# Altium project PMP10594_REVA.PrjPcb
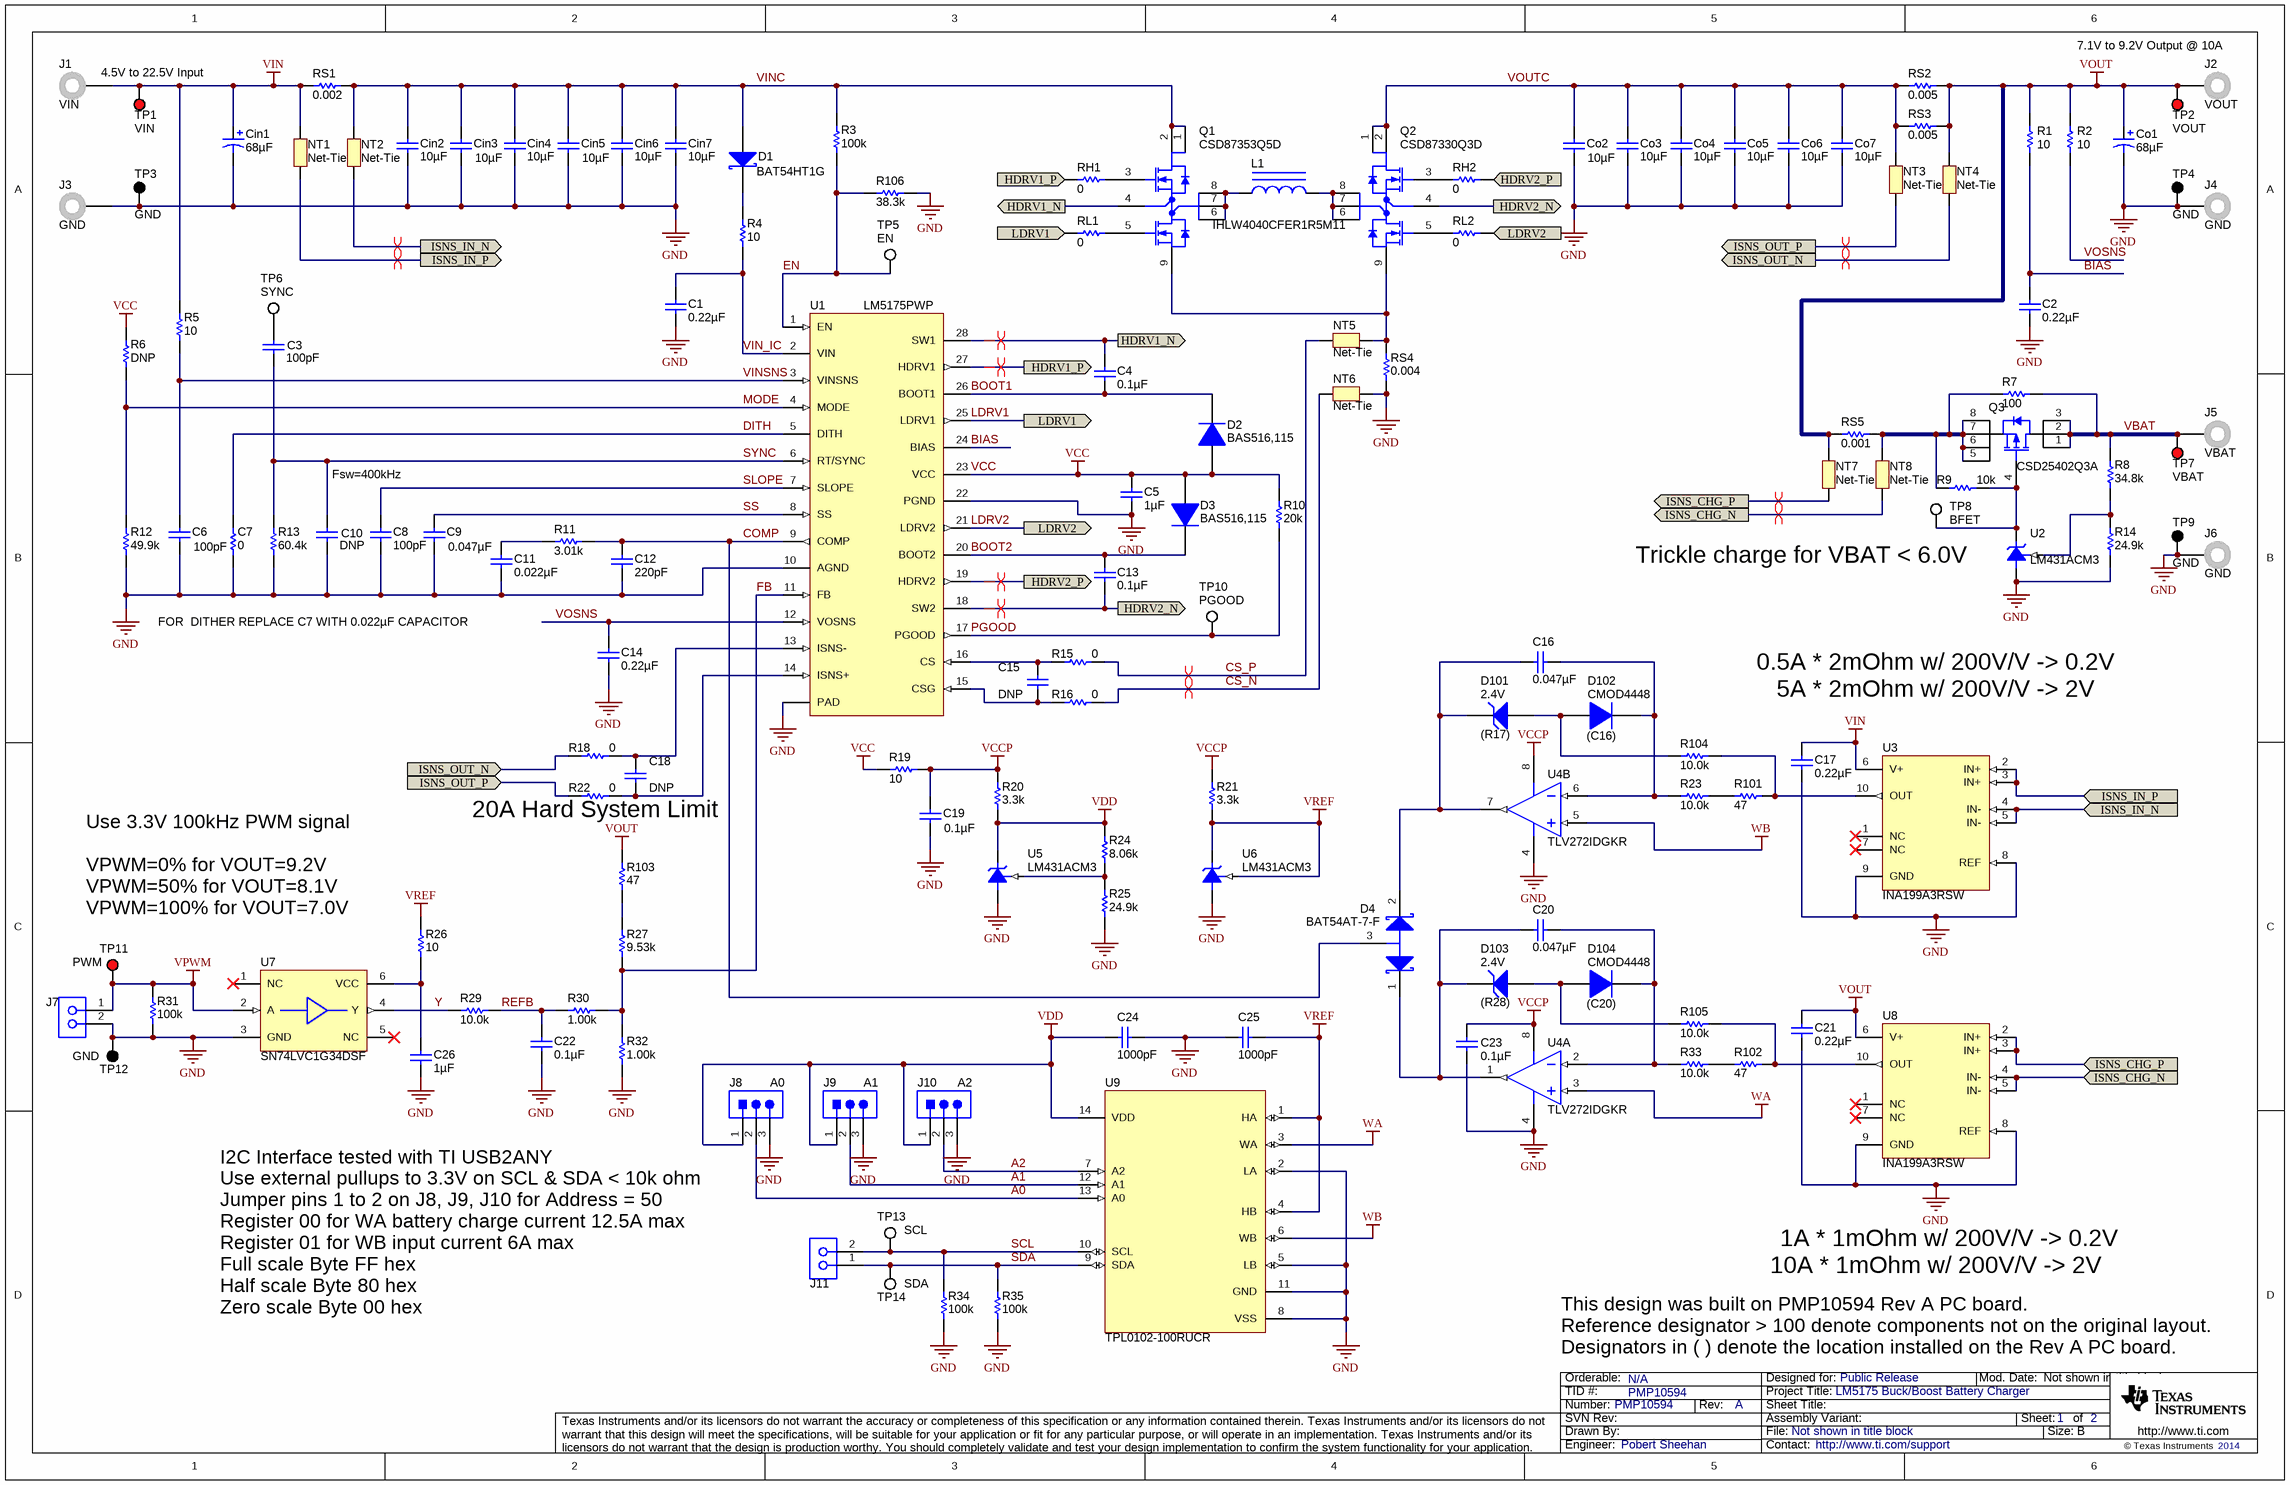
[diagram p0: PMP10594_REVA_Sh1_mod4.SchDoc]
TID: PMP10594; TechSupport: http://www.ti.com/support; SCH_Rev: A; PRJ_Title: LM5175 Buck/Boost Battery Charger; PRJ_Number: PMP10594; PRJ_Engineer: Pobert Sheehan; PRJ_Customer: Public Release; PCB_Rev: A; PCB_Layout: Robert Sheehan; EVM_Orderable: N/A; CopyrightYear: 2014
2 sheets, 158 parts. Net scope: flat (ports and power ports of the same name join across sheets).
Board file: PMP10594_REVA.PcbDoc
Sheets:
  PMP10594_REVA_Sh1_mod4.SchDoc
  PMP10594_REVA_Sh2.SchDoc

## Sheet PMP10594_REVA_Sh1_mod4.SchDoc
size 431 x 279 mm; Date: Not shown in title block; ApprovedBy: Not shown in title block; CheckedBy: Not shown in title block; Author: Not shown in title block; CompanyName: Not shown in title block; Engineer: Not shown in title block; Organization: Not shown in title block; Address1: Not shown in title block; Address2: Not shown in title block; Address3: Not shown in title block; Address4: Not shown in title block; DocumentNumber: 1; Revision: Use project parameter SCH_Rev; SheetNumber: 1; SheetTotal: 2; PageSetup: Record=PageOptions¦CenterHorizontal=True¦CenterVertical=True¦PrintScale=1.00¦XCorrection=1.00¦YCorrection=1.00¦PrintKind=0¦BorderSize=5000000¦LeftOffset=0¦BottomOffset=0¦Orientation=2¦PaperLength=1000¦PaperWidth=1000¦Scale=100¦PaperSource=15¦PrintQuality=600¦MediaType=1¦DitherType=10¦PaperKind=Letter¦PrintScaleMode=1

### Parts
C1  ValueDisplayed: 0.22µF  [0603L]  (hidden comment: C1608X7R1H224K080AB)
C2  ValueDisplayed: 0.22µF  [0603L]  (hidden comment: C1608X7R1H224K080AB)
C3  ValueDisplayed: 100pF  [0603L]  (hidden comment: CGA3E2NP01H101J080AA)
C4  ValueDisplayed: 0.1µF  [0603L]  (hidden comment: 06033C104JAT2A)
C5  ValueDisplayed: 1µF  [0603L]  (hidden comment: GRM188R71C105KA12D)
C6  ValueDisplayed: 100pF  [0603L]  (hidden comment: GRM1885C1H101JA01D)
C7  ValueDisplayed: 0  [0603L]  (hidden comment: CRCW06030000Z0EA)
C8  ValueDisplayed: 100pF  [0603L]  (hidden comment: GRM1885C1H101JA01D)
C9  ValueDisplayed: 0.047µF  [0603L]  (hidden comment: GRM188R71H473KA61D)
C10  DNP  [0603L]
C11  ValueDisplayed: 0.022µF  [0603L]  (hidden comment: GRM188R71H223KA01D)
C12  ValueDisplayed: 220pF  [0603L]  (hidden comment: GRM1885C1H221JA01D)
C13  ValueDisplayed: 0.1µF  [0603L]  (hidden comment: 06033C104JAT2A)
C14  ValueDisplayed: 0.22µF  [0603L]  (hidden comment: C1608X7R1H224K080AB)
C15  DNP  [0603L]
C16  ValueDisplayed: 0.047µF  [0603L]  (hidden comment: GRM188R71H473KA61D)
C17  ValueDisplayed: 0.22µF  [0603_HV]  (hidden comment: C1608X7R1H224K080AB)
C18  DNP  [0603L]
C19  ValueDisplayed: 0.1µF  [0603L]  (hidden comment: 06033C104JAT2A)
C20  ValueDisplayed: 0.047µF  [0603L]  (hidden comment: GRM188R71H473KA61D)
C21  ValueDisplayed: 0.22µF  [0603_HV]  (hidden comment: C1608X7R1H224K080AB)
C22  ValueDisplayed: 0.1µF  [0603L]  (hidden comment: 06033C104JAT2A)
C23  ValueDisplayed: 0.1µF  [0603L]  (hidden comment: 06033C104JAT2A)
C24  ValueDisplayed: 1000pF  [0603L]  (hidden comment: GRM188R71H102KA01D)
C25  ValueDisplayed: 1000pF  [0603L]  (hidden comment: GRM188R71H102KA01D)
C26  ValueDisplayed: 1µF  [0603L]  (hidden comment: GRM188R71C105KA12D)
Cin1  ValueDisplayed: 68µF  [SM_RADIAL_8MM]  (hidden comment: EEHZC1H680P)
Cin2  ValueDisplayed: 10µF  [1210L]  (hidden comment: GRM32ER71H106KA12L)
Cin3  ValueDisplayed: 10µF  [1210L]  (hidden comment: GRM32ER71H106KA12L)
Cin4  ValueDisplayed: 10µF  [1210L]  (hidden comment: GRM32ER71H106KA12L)
Cin5  ValueDisplayed: 10µF  [1210L]  (hidden comment: GRM32ER71H106KA12L)
Cin6  ValueDisplayed: 10µF  [1210L]  (hidden comment: GRM32ER71H106KA12L)
Cin7  ValueDisplayed: 10µF  [1210L]  (hidden comment: GRM32ER71H106KA12L)
Co1  ValueDisplayed: 68µF  [SM_RADIAL_8MM]  (hidden comment: EEHZC1H680P)
Co2  ValueDisplayed: 10µF  [1210L]  (hidden comment: GRM32ER71H106KA12L)
Co3  ValueDisplayed: 10µF  [1210L]  (hidden comment: GRM32ER71H106KA12L)
Co4  ValueDisplayed: 10µF  [1210L]  (hidden comment: GRM32ER71H106KA12L)
Co5  ValueDisplayed: 10µF  [1210L]  (hidden comment: GRM32ER71H106KA12L)
Co6  ValueDisplayed: 10µF  [1210L]  (hidden comment: GRM32ER71H106KA12L)
Co7  ValueDisplayed: 10µF  [1210L]  (hidden comment: GRM32ER71H106KA12L)
D1  BAT54HT1G  [sod-323]
D2  BAS516,115  [SOD-523]
D3  BAS516,115  [SOD-523]
D4  BAT54AT-7-F  [SOT-523]
D101  (R17)  value 2.4V  [sod-323]
D102  (C16)  PartNumber: CMOD4448  [sod-523]
D103  (R28)  value 2.4V  [sod-323]
D104  (C20)  PartNumber: CMOD4448  [sod-523]
J1  VIN  [Johnson_108-0740-001]
J2  VOUT  [Johnson_108-0740-001]
J3  GND  [Johnson_108-0740-001]
J4  GND  [Johnson_108-0740-001]
J5  VBAT  [Johnson_108-0740-001]
J6  GND  [Johnson_108-0740-001]
J7  1727010  [PhoenixConact_1727010]  (value not drawn)
J8  A0  [TE_5-146278-3]
J9  A1  [TE_5-146278-3]
J10  A2  [TE_5-146278-3]
J11  1727010  [PhoenixConact_1727010]  (value not drawn)
L1  IHLW4040CFER1R5M11  [IHLW-4040CF]
NT1  Net-Tie  [Net-Tie_10mil]  (net tie, no BOM)
NT2  Net-Tie  [Net-Tie_10mil]  (net tie, no BOM)
NT3  Net-Tie  [Net-Tie_10mil]  (net tie, no BOM)
NT4  Net-Tie  [Net-Tie_10mil]  (net tie, no BOM)
NT5  Net-Tie  [Net-Tie_10mil]  (net tie, no BOM)
NT6  Net-Tie  [Net-Tie_10mil]  (net tie, no BOM)
NT7  Net-Tie  [Net-Tie_10mil]  (net tie, no BOM)
NT8  Net-Tie  [Net-Tie_10mil]  (net tie, no BOM)
Q1  CSD87353Q5D  [TRANS_NexFET_Q5D]
Q2  CSD87330Q3D  [TRANS_NexFET_Q3D]
Q3  CSD25402Q3A  [TRANS_NexFET_Q3A]
R1  value 10  [0603L]  (hidden comment: CRCW060310R0JNEA)
R2  ValueDisplayed: 10  [0603L]  (hidden comment: CRCW060310R0JNEA)
R3  ValueDisplayed: 100k  [0603L]  (hidden comment: CRCW0603100KJNEA)
R4  ValueDisplayed: 10  [0603L]  (hidden comment: CRCW060310R0JNEA)
R5  ValueDisplayed: 10  [0603L]  (hidden comment: CRCW060310R0JNEA)
R6  DNP  [0603L]
R7  ValueDisplayed: 100  [2010]  (hidden comment: CRCW2010100RJNEF)
R8  ValueDisplayed: 34.8k  [0603L]  (hidden comment: CRCW060334K8FKEA)
R9  ValueDisplayed: 10k  [0603L]  (hidden comment: CRCW060310K0JNEA)
R10  ValueDisplayed: 20k  [0603L]  (hidden comment: CRCW060320K0JNEA)
R11  ValueDisplayed: 3.01k  [0603L]  (hidden comment: CRCW06033K01FKEA)
R12  ValueDisplayed: 49.9k  [0603L]  (hidden comment: CRCW060349K9FKEA)
R13  ValueDisplayed: 60.4k  [0603L]  (hidden comment: CRCW060360K4FKEA)
R14  ValueDisplayed: 24.9k  [0603L]  (hidden comment: CRCW060324K9FKEA)
R15  value 0  [0603L]  (hidden comment: CRCW06030000Z0EA)
R16  value 0  [0603L]  (hidden comment: CRCW06030000Z0EA)
R18  value 0  [0603L]  (hidden comment: CRCW06030000Z0EA)
R19  ValueDisplayed: 10  [0603L]  (hidden comment: CRCW060310R0JNEA)
R20  ValueDisplayed: 3.3k  [0603L]  (hidden comment: CRCW06033K30JNEA)
R21  ValueDisplayed: 3.3k  [0603L]  (hidden comment: CRCW06033K30JNEA)
R22  value 0  [0603L]  (hidden comment: CRCW06030000Z0EA)
R23  ValueDisplayed: 10.0k  [0603L]  (hidden comment: CRCW060310K0FKEA)
R24  ValueDisplayed: 8.06k  [0603L]  (hidden comment: CRCW06038K06FKEA)
R25  ValueDisplayed: 24.9k  [0603L]  (hidden comment: CRCW060324K9FKEA)
R26  ValueDisplayed: 10  [0603L]  (hidden comment: CRCW060310R0JNEA)
R27  ValueDisplayed: 9.53k  [0603L]  (hidden comment: CRCW06039K53FKEA)
R29  ValueDisplayed: 10.0k  [0603L]  (hidden comment: CRCW060310K0FKEA)
R30  ValueDisplayed: 1.00k  [0603L]  (hidden comment: CRCW06031K00FKEA)
R31  ValueDisplayed: 100k  [0603L]  (hidden comment: CRCW0603100KJNEA)
R32  ValueDisplayed: 1.00k  [0603L]  (hidden comment: CRCW06031K00FKEA)
R33  ValueDisplayed: 10.0k  [0603L]  (hidden comment: CRCW060310K0FKEA)
R34  ValueDisplayed: 100k  [0603L]  (hidden comment: CRCW0603100KJNEA)
R35  ValueDisplayed: 100k  [0603L]  (hidden comment: CRCW0603100KJNEA)
R101  ValueDisplayed: 47  [0603L]  (hidden comment: CRCW060347R0JNEA)
R102  ValueDisplayed: 47  [0603L]  (hidden comment: CRCW060347R0JNEA)
R103  ValueDisplayed: 47  [0603L]  (hidden comment: CRCW060347R0JNEA)
R104  ValueDisplayed: 10.0k  [0603L]  (hidden comment: CRCW060310K0FKEA)
R105  ValueDisplayed: 10.0k  [0603L]  (hidden comment: CRCW060310K0FKEA)
R106  ValueDisplayed: 38.3k  [0603L]  (hidden comment: CRCW060338K3FKEA)
RH1  value 0  [0603L]  (hidden comment: CRCW06030000Z0EA)
RH2  value 0  [0603L]  (hidden comment: CRCW06030000Z0EA)
RL1  value 0  [0603L]  (hidden comment: CRCW06030000Z0EA)
RL2  value 0  [0603L]  (hidden comment: CRCW06030000Z0EA)
RS1  ValueDisplayed: 0.002  [1206]  (hidden comment: CSNL1206FT2L00)
RS2  ValueDisplayed: 0.005  [2010]  (hidden comment: CSNL2010FT5L00)
RS3  ValueDisplayed: 0.005  [2010]  (hidden comment: CSNL2010FT5L00)
RS4  ValueDisplayed: 0.004  [2512]  (hidden comment: CSNL2512FT4L00)
RS5  ValueDisplayed: 0.001  [2010]  (hidden comment: CSNL2010FT1L00)
TP1  VIN  [Keystone5000]
TP2  VOUT  [Keystone5000]
TP3  GND  [Keystone5001]
TP4  GND  [Keystone5001]
TP5  EN  [Keystone5002]
TP6  SYNC  [Keystone5002]
TP7  VBAT  [Keystone5000]
TP8  BFET  [Keystone5002]
TP9  GND  [Keystone5001]
TP10  PGOOD  [Keystone5002]
TP11  PWM  [Keystone5000]
TP12  GND  [Keystone5001]
TP13  SCL  [Keystone5002]
TP14  SDA  [Keystone5002]
U1  LM5175PWP  [PWP0028F_N]
U2  LM431ACM3  [MF03A_N]
U3  INA199A3RSW  [RSW0010A]
U4  TLV272IDGKR  [DGK0008A_N]  (parts A,B of 2)
U5  LM431ACM3  [MF03A_N]
U6  LM431ACM3  [MF03A_N]
U7  SN74LVC1G34DSF  [DSF0006A]
U8  INA199A3RSW  [RSW0010A]
U9  TPL0102-100RUCR  [RUC0014A]

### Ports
HDRV1_N, HDRV1_P (out), HDRV2_N, HDRV2_P (out), ISNS_CHG_N (in), ISNS_CHG_N (out), ISNS_CHG_P (in), ISNS_CHG_P (out), ISNS_IN_N (in), ISNS_IN_N (out), ISNS_IN_P (in), ISNS_IN_P (out), ISNS_OUT_N (in), ISNS_OUT_N (out), ISNS_OUT_P (in), ISNS_OUT_P (out), LDRV1 (out), LDRV2 (out)

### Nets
GND: C1.2 C2.2 C5.2 C6.1 C7.1 C8.2 C9.2 C10.1 C11.2 C12.2 C14.2 C17.2 C19.2 C21.2 C22.2 C23.2 C24.2 C25.1 C26.2 Cin1.2(-) Cin2.2 Cin3.2 Cin4.2 Cin5.2 Cin6.2 Cin7.2 Co1.2(-) Co2.2 Co3.2 Co4.2 Co5.2 Co6.2 Co7.2 J3.1 J4.1 J6.1 J7.2 J8.3 J9.3 J10.3 NT6.1 R12.1 R13.1 R14.1 R25.1 R31.1 R32.1 R34.1 R35.1 R106.1 RS4.1 TP3.1 TP4.1 TP9.1 TP12.1 U1.10(AGND) U1.22(PGND) U1.29(PAD) U2.3(A) U3.8(REF) U3.9(GND) U4.4(GND) U5.3(A) U6.3(A) U7.3(GND) U8.8(REF) U8.9(GND) U9.2(LA) U9.5(LB) U9.8(VSS) U9.11(GND)
VCC: C5.1 D2.2(A) D3.2(A) R6.2 R10.2 R19.2 U1.23(VCC)
VCCP: C19.1 C23.1 R19.1 R20.1 R21.1 U4.8(VDD)
VDD: C24.1 J8.1 J9.1 J10.1 R20.2 R24.2 U5.1(K) U9.14(VDD)
VIN: C17.1 Cin1.1(+) J1.1 NT1.1 R5.1 RS1.1 TP1.1 U3.6(V+)
VOUT: C21.1 Co1.1(+) J2.1 NT4.2 NT7.2 R1.2 R2.2 R103.1 RS2.2 RS3.2 RS5.1 TP2.1 U8.6(V+)
VPWM: J7.1 R31.2 TP11.1 U7.2(A)
VREF: C25.2 R21.2 R26.2 U6.1(K) U6.2(REF) U9.1(HA) U9.4(HB)
WA: U4.3(IN1+) U9.3(WA)
WB: U4.5(IN2+) U9.6(WB)
A0: J8.2 U9.13(A0)
A1: J9.2 U9.12(A1)
A2: J10.2 U9.7(A2)
BIAS: C2.1 R1.1 U1.24(BIAS)
BOOT1: C4.1 D2.1(K) U1.26(BOOT1)
BOOT2: C13.2 D3.1(K) U1.20(BOOT2)
COMP: C12.1 D4.3(K) R11.2 U1.9(COMP)
CS_N: NT6.2 R16.2
CS_P: NT5.2 R15.2
DITH: C7.2 U1.5(DITH)
EN: R3.1 R106.2 TP5.1 U1.1(EN)
FB: R27.1 R30.2 R32.2 U1.11(FB)
HDRV1_N: C4.2 Q1.4(TGR) U1.28(SW1) ; port HDRV1_N
HDRV1_P: RH1.1 U1.27(HDRV1) ; port HDRV1_P
HDRV2_N: C13.1 Q2.4(TGR) U1.18(SW2) ; port HDRV2_N
HDRV2_P: RH2.2 U1.19(HDRV2) ; port HDRV2_P
ISNS_CHG_N: NT8.1 U8.4(IN-) U8.5(IN-) ; port ISNS_CHG_N
ISNS_CHG_P: NT7.1 U8.2(IN+) U8.3(IN+) ; port ISNS_CHG_P
ISNS_IN_N: NT2.1 U3.4(IN-) U3.5(IN-) ; port ISNS_IN_N
ISNS_IN_P: NT1.2 U3.2(IN+) U3.3(IN+) ; port ISNS_IN_P
ISNS_OUT_N: NT4.1 R18.1 ; port ISNS_OUT_N
ISNS_OUT_P: NT3.1 R22.1 ; port ISNS_OUT_P
LDRV1: RL1.1 U1.25(LDRV1) ; port LDRV1
LDRV2: RL2.2 U1.21(LDRV2) ; port LDRV2
MODE: R6.1 R12.2 U1.4(MODE)
PGOOD: R10.1 TP10.1 U1.17(PGOOD)
REFB: C22.1 R29.1 R30.1
SCL: J11.2 R34.2 TP13.1 U9.10(SCL)
SDA: J11.1 R35.2 TP14.1 U9.9(SDA)
SLOPE: C8.1 U1.7(SLOPE)
SS: C9.1 U1.8(SS)
SYNC: C3.2 C10.2 R13.2 U1.6(RT/SYNC)
VBAT: J5.1 Q3.1(D) Q3.2(D) Q3.3(D) R7.2 R8.2 TP7.1
VIN_IC: C1.1 R4.1 U1.2(VIN)
VINC: Cin2.1 Cin3.1 Cin4.1 Cin5.1 Cin6.1 Cin7.1 D1.2(A) NT2.2 Q1.1(VIN) Q1.2(VIN) R3.2 RS1.2
VINSNS: C6.2 R5.2 U1.3(VINSNS)
VOSNS: C14.1 R2.1 U1.12(VOSNS)
VOUTC: Co2.1 Co3.1 Co4.1 Co5.1 Co6.1 Co7.1 NT3.2 Q2.1(VIN) Q2.2(VIN) RS2.1 RS3.1
Y: R29.2 U7.4(Y)
NetC3_1: C3.1 TP6.1
NetC11_1: C11.1 R11.1
NetC15_1: C15.1 R15.1 U1.16(CS)
NetC15_2: C15.2 R16.1 U1.15(CSG)
NetC16_1: C16.1 D4.2(A2) D101.1(K) U4.7(OUT2)
NetC16_2: C16.2 D102.1(K) R23.1 U4.6(IN2-)
NetC18_1: C18.1 R18.2 U1.13(ISNS-)
NetC18_2: C18.2 R22.2 U1.14(ISNS+)
NetC20_1: C20.1 D4.1(A1) D103.1(K) U4.1(OUT1)
NetC20_2: C20.2 D104.1(K) R33.1 U4.2(IN1-)
NetC26_1: C26.1 R26.1 U7.6(VCC)
NetD1_1: D1.1(K) R4.2
NetD101_2: D101.2(A) D102.2(A) R104.1
NetD103_2: D103.2(A) D104.2(A) R105.1
NetL1_1: L1.1 Q1.6(VSW) Q1.7(VSW) Q1.8(VSW)
NetL1_2: L1.2 Q2.6(VSW) Q2.7(VSW) Q2.8(VSW)
NetNT5_1: NT5.1 Q1.9(PGND) Q2.9(PGND) RS4.2
NetNT8_2: NT8.2 Q3.5(S) Q3.6(S) Q3.7(S) Q3.8(S) R7.1 R9.1 RS5.2
NetQ1_3: Q1.3(TG) RH1.2
NetQ1_5: Q1.5(BG) RL1.2
NetQ2_3: Q2.3(TG) RH2.1
NetQ2_5: Q2.5(BG) RL2.1
NetQ3_4: Q3.4(G) R9.2 TP8.1 U2.1(K)
NetR8_1: R8.1 R14.2 U2.2(REF)
NetR23_2: R23.2 R101.2
NetR24_1: R24.1 R25.2 U5.2(REF)
NetR27_2: R27.2 R103.2
NetR33_2: R33.2 R102.2
NetR101_1: R101.1 R104.2 U3.10(OUT)
NetR102_1: R102.1 R105.2 U8.10(OUT)

Not connected (* = marked no-connect by the designer): U3 1(NC)* 7(NC)*; U7 1(NC)* 5(NC)*; U8 1(NC)* 7(NC)*

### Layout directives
differential pair: CS_N, CS_P, HDRV1_N, HDRV1_P, HDRV2_N, HDRV2_P, ISNS_CHG_N, ISNS_CHG_P, ISNS_IN_N, ISNS_IN_P, ISNS_OUT_N, ISNS_OUT_P

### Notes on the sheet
- 4.5V to 22.5V Input
- 7.1V to 9.2V Output @ 10A
- Fsw=400kHz
- Trickle charge for VBAT < 6.0V
- FOR  DITHER REPLACE C7 WITH 0.022µF CAPACITOR
- 0.5A * 2mOhm w/ 200V/V -> 0.2V
- 5A * 2mOhm w/ 200V/V -> 2V
- (near R22) 20A Hard System Limit
- Use 3.3V 100kHz PWM signal
  VPWM=0% for VOUT=9.2V
  VPWM=50% for VOUT=8.1V
  VPWM=100% for VOUT=7.0V
- 1A * 1mOhm w/ 200V/V -> 0.2V
- 10A * 1mOhm w/ 200V/V -> 2V
- (near J8) I2C Interface tested with TI USB2ANY
  Use external pullups to 3.3V on SCL & SDA < 10k ohm
  Jumper pins 1 to 2 on J8, J9, J10 for Address = 50
  Register 00 for WA battery charge current 12.5A max
  Register 01 for WB input current 6A max
  Full scale Byte FF hex
  Half scale Byte 80 hex
  Zero scale Byte 00 hex
- This design was built on PMP10594 Rev A PC board.
  Reference designator > 100 denote components not on the original layout.
  Designators in ( ) denote the location installed on the Rev A PC board.

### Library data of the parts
C1 C2 C17 C21 = C1608X7R1H224K080AB: CAP, CERM, 0.22uF, 50V, +/-10%, X7R, 0603; Manufacturer: TDK; Polarized: N; CompType: Capacitor; U/M: EA; Cap_F: 0.00000022; Tolerance_%: 10; Value1: Unknown; VDC_V: 50; TaMin_C: -55; TaMax_C: 125; Cap_Case: 0603
C3 = CGA3E2NP01H101J080AA: CAP, CERM, 100pF, 50V, +/-5%, C0G/NP0, 0603; Manufacturer: TDK; Polarized: N; CompType: Capacitor; U/M: EA; Cap_F: 0.0000000001; Tolerance_%: 5; Value1: Unknown; VDC_V: 50; TaMin_C: -55; TaMax_C: 150; Cap_Case: 0603
C4 C13 C19 C22 C23 = 06033C104JAT2A: CAP, CERM, 0.1 µF, 25 V, +/- 5%, X7R, 0603; Manufacturer: AVX; Polarized: N; CompType: Capacitor; Value: 0.1uF; U/M: EA; Cap_F: 0.0000001; Tolerance_%: 5; ESR_ohm: 0.05; Value1: 0.05 ohm; VDC_V: 25; Value2: 25V; TaMin_C: -55; TaMax_C: 125; Cap_Case: 0603
C5 = GRM188R71C105KA12D: CAP, CERM, 1uF, 16V, +/-10%, X7R, 0603; Manufacturer: MuRata; Polarized: N; CompType: Capacitor; U/M: EA; Cap_F: 0.000001; Tolerance_%: 10; ESR_Ohm: 0.011; Value1: 0.011 ohm; VDC_V: 16; TaMin_C: -55; TaMax_C: 125; Cap_Case: 0603
C6 C10 C15 C18 = GRM1885C1H101JA01D: CAP, CERM, 100pF, 50V, +/-5%, C0G/NP0, 0603; Manufacturer: MuRata; Polarized: N; CompType: Capacitor; U/M: EA; Cap_F: 0.0000000001; Tolerance_%: 5; Value1: Unknown; VDC_V: 50; TaMin_C: -55; TaMax_C: 125; Cap_Case: 0603
C7 = CRCW06030000Z0EA: RES, 0, 5%, 0.1 W, 0603; Manufacturer: Vishay-Dale; CompType: Resistor; Value: 0; Tolerance_%: 5; Value2: 0.1W; VDC_V: 75; TempCo: 200 ppm/C; U/M: EA; Value_Code: 0000; Power_W: 0.1; EIA_Code: E24
C8 = GRM1885C1H101JA01D: CAP, CERM, 100 pF, 50 V, +/- 5%, C0G/NP0, 0603; Manufacturer: MuRata; Polarized: N; CompType: Capacitor; Value: 100pF; U/M: EA; Cap_F: 0.0000000001; Tolerance_%: 5; Value1: Unknown; VDC_V: 50; Value2: 50V; TaMin_C: -55; TaMax_C: 125; Cap_Case: 0603
C9 C16 C20 = GRM188R71H473KA61D: CAP, CERM, 0.047 µF, 50 V, +/- 10%, X7R, 0603; Manufacturer: MuRata; Polarized: N; CompType: Capacitor; Value: 0.047uF; U/M: EA; Cap_F: 0.000000047; Tolerance_%: 10; Value1: Unknown; VDC_V: 50; Value2: 50V; TaMin_C: -55; TaMax_C: 125; Cap_Case: 0603
C11 = GRM188R71H223KA01D: CAP, CERM, 0.022 µF, 50 V, +/- 10%, X7R, 0603; Manufacturer: MuRata; Polarized: N; CompType: Capacitor; Value: 0.022uF; U/M: EA; Cap_F: 0.000000022; Tolerance_%: 10; Value1: Unknown; VDC_V: 50; Value2: 50V; TaMin_C: -55; TaMax_C: 125; Cap_Case: 0603
C12 = GRM1885C1H221JA01D: CAP, CERM, 220 pF, 50 V, +/- 5%, C0G/NP0, 0603; Manufacturer: MuRata; Polarized: N; CompType: Capacitor; Value: 220pF; U/M: EA; Cap_F: 0.00000000022; Tolerance_%: 5; Value1: Unknown; VDC_V: 50; Value2: 50V; TaMin_C: -55; TaMax_C: 125; Cap_Case: 0603
C14 = C1608X7R1H224K080AB: CAP, CERM, 0.22 µF, 50 V, +/- 10%, X7R, 0603; Manufacturer: TDK; Polarized: N; CompType: Capacitor; Value: 0.22uF; U/M: EA; Cap_F: 0.00000022; Tolerance_%: 10; Value1: Unknown; VDC_V: 50; Value2: 50V; TaMin_C: -55; TaMax_C: 125; Cap_Case: 0603
C24 C25 = GRM188R71H102KA01D: CAP, CERM, 1000 pF, 50 V, +/- 10%, X7R, 0603; Manufacturer: MuRata; Polarized: N; CompType: Capacitor; Value: 1000pF; U/M: EA; Cap_F: 0.000000001; Tolerance_%: 10; Value1: Unknown; VDC_V: 50; Value2: 50V; TaMin_C: -55; TaMax_C: 125; Cap_Case: 0603
C26 = GRM188R71C105KA12D: CAP, CERM, 1 µF, 16 V, +/- 10%, X7R, 0603; Manufacturer: MuRata; Polarized: N; CompType: Capacitor; Value: 1uF; U/M: EA; Cap_F: 0.000001; Tolerance_%: 10; ESR_ohm: 0.011; Value1: 0.011 ohm; VDC_V: 16; Value2: 16V; TaMin_C: -55; TaMax_C: 125; Cap_Case: 0603
Cin1 Co1 = EEHZC1H680P: CAP, AL, 68 µF, 50 V, +/- 20%, 30 ohm, SMD; Manufacturer: Panasonic; Polarized: Y; CompType: Capacitor; Value: 68uF; U/M: EA; Cap_F: 0.000068; Tolerance_%: 20; Value1: 30 ohm; VDC_V: 50; Value2: 50V; ESR_ohm: 30; IRMS_A: 1.25; TaMin_C: -55; TaMax_C: 125
Cin2-Cin7 = GRM32ER71H106KA12L: CAP, CERM, 10uF, 50V, +/-10%, X7R, 1210; Manufacturer: MuRata; Polarized: N; CompType: Capacitor; U/M: EA; Cap_F: 0.00001; Tolerance_%: 10; Value1: Unknown; VDC_V: 50; TaMin_C: -55; TaMax_C: 125; Cap_Case: 1210
Co2-Co7 = GRM32ER71H106KA12L: CAP, CERM, 10 µF, 50 V, +/- 10%, X7R, 1210; Manufacturer: MuRata; Polarized: N; CompType: Capacitor; Value: 10uF; U/M: EA; Cap_F: 0.00001; Tolerance_%: 10; Value1: Unknown; VDC_V: 50; Value2: 50V; TaMin_C: -55; TaMax_C: 125; Cap_Case: 1210
D1 = BAT54HT1G: Diode, Schottky, 30V, 0.2A, SOD-323; Manufacturer: ON Semiconductor; U/M: EA; Vf_V: 0.35; Value2: 0.35V; Io_A: 0.2; Vr_V: 30
D2 D3 = BAS516,115: Diode, Switching, 100V, 0.25A, SOD-523; Manufacturer: NXP Semiconductor; U/M: EA; Vf_V: 1.25; Value2: 1.25V; Io_A: 0.25; Vr_V: 100; TJmax_C: 150
D4 = BAT54AT-7-F: Diode, Schottky, 30 V, 0.2 A, SOT-523; Manufacturer: Diodes Inc.; U/M: EA; Vf_V: 0.7; Value: 30V; Value1: 0.2A; Value2: 0.7V; Io_A: 0.2; Vr_V: 30; TJmax_C: 125
D101 D103 = MMSZ5221BS-7-F: Diode, Zener, 2.4 V, 200 mW, SOD-323; Manufacturer: Diodes Inc.; U/M: EA; Value1: 0.2W; SymbolCreator: a0412235; Power_W: 0.2; Vz_V: 2.4; RJA_CperW: 350
D102 D104 = CMDD4448: Diode, Ultrafast, 75 V, 0.25 A, SOD-523; Manufacturer: Central Semiconductor; U/M: EA; Vf_V: 1.2; Value: 75V; Value1: 0.25A; Value2: 1.2V; Io_A: 0.25; Vr_V: 75; TJmax_C: 175
J1-J6 = 108-0740-001: Standard Banana Jack, Uninsulated, 15A; Manufacturer: Emerson Network Power; SymbolCreator: a0412235; CompType: Connector; U/M: EA
J7 J11 = 1727010: Conn Term Block, 2POS, 3.81mm PCB; Manufacturer: Phoenix Contact; CompType: Terminal Block; U/M: EA; Value: 2x1
J8-J10 = 5-146278-3: Header, 100mil, 3x1, Tin, TH; Manufacturer: TE Connectivity; SymbolCreator: a0799628; U/M: EA
L1 = IHLW4040CFER1R5M11: Inductor, Shielded, Powdered Iron, 1.5 µH, 14.5 A, 0.0044 ohm, SMD, Winged Terminal; Manufacturer: Vishay-Dale; Value: 1.5uH; ValueDisplayed: 1.5µH; Ind_H: 1.5E-6; Imax_A: 15; Irms: 20A @ 40C rise; Isat: 14.5A @ 20% inductance drop; DCR_ohm: 0.0044; Value2: 14.5A
NT1-NT8 = Net-Tie: Single point connection between nets.; SymbolCreator: codlsc
Q1 = CSD87353Q5D: Manufacturer: Texas Instruments; Alternate Manufacturer: None; CompType: MOSFET; U/M: EA; ChType: N
Q2 = CSD87330Q3D: MOSFET, N/P-CH, 30 V, 20 A, 3.4x1.4x3.4mm; Manufacturer: Texas Instruments; Alternate Manufacturer: None; SymbolCreator: a0799628; U/M: EA; ChType: N; Value: 30V; VdsMax_V: 30; Value1: ? ohm; Value2: 5.8 nC; QgTyp_nC: 5.8; Vgs_V: 2.1; IdsMax_A: 20
Q3 = CSD25402Q3A: MOSFET, P-CH, -20 V, -15 A, SON 3.3x3.3mm; Manufacturer: Texas Instruments; Alternate Manufacturer: None; SymbolCreator: a0411947; U/M: EA; ChType: P; Value: -20V; Value1: 0.0077 ohm; Rdson45_ohm: 0.0077; Value2: 7.5 nC; QgTyp_nC: 7.5; Vgs_V: 12
R1 = CRCW060310R0JNEA: RES, 10, 5%, 0.1 W, 0603; Manufacturer: Vishay-Dale; CompType: Resistor; Value_Code: 10R0; Tolerance_%: 5; Power_W: 0.1; Value2: 0.1W; VDC_V: 75; TempCo: 200 ppm/C; EIA_Code: E24; U/M: EA
R2 = CRCW060310R0JNEA: RES, 10, 5%, 0.1 W, 0603; Manufacturer: Vishay-Dale; CompType: Resistor; Value_Code: 10R0; Tolerance_%: 5; Power_W: 0.1; Value2: 0.1W; VDC_V: 75; TempCo: 200 ppm/C; EIA_Code: E24; U/M: EA; Value: 10
R3 R31 R34 R35 = CRCW0603100KJNEA: RES, 100 k, 5%, 0.1 W, 0603; Manufacturer: Vishay-Dale; CompType: Resistor; Value: 100k; Res_ohm: 100000; Tolerance_%: 5; Power_W: 0.1; Value2: 0.1W; VDC_V: 75; TempCo: 200 ppm/C; EIA_Code: E24; U/M: EA
R4 R5 R19 R26 = CRCW060310R0JNEA: RES, 10, 5%, 0.1 W, 0603; Manufacturer: Vishay-Dale; CompType: Resistor; Value: 10; Value_Code: 10R0; Tolerance_%: 5; Power_W: 0.1; Value2: 0.1W; VDC_V: 75; TempCo: 200 ppm/C; EIA_Code: E24; U/M: EA
R6 = CRCW06030000Z0EA: RES, 0, 5%, 0.1 W, 0603; Manufacturer: Vishay-Dale; CompType: Resistor; Value: 0; Value_Code: 0000; Tolerance_%: 5; Power_W: 0.1; Value2: 0.1W; VDC_V: 75; TempCo: 200 ppm/C; EIA_Code: E24; U/M: EA
R7 = CRCW2010100RJNEF: RES, 100, 5%, 0.75 W, 2010; Manufacturer: Vishay-Dale; CompType: Resistor; Value: 100; Tolerance_%: 5; Power_W: 0.75; TempCo: 200 ppm/C; U/M: EA; Value_Code: 100R; Value2: 0.75W; VDC_V: 400; EIA_Code: E24
R8 = CRCW060334K8FKEA: RES, 34.8 k, 1%, 0.1 W, 0603; Manufacturer: Vishay-Dale; CompType: Resistor; Res_ohm: 34800; Value_Code: 34k8; Tolerance_%: 1; Power_W: 0.1; Value2: 0.1W; VDC_V: 75; TempCo: 100 ppm/C; EIA_Code: E96; U/M: EA; Value: 34.8k
R9 = CRCW060310K0JNEA: RES, 10 k, 5%, 0.1 W, 0603; Manufacturer: Vishay-Dale; CompType: Resistor; Res_ohm: 10000; Value_Code: 10k0; Tolerance_%: 5; Power_W: 0.1; Value2: 0.1W; VDC_V: 75; TempCo: 200 ppm/C; EIA_Code: E24; U/M: EA; Value: 10k
R10 = CRCW060320K0JNEA: RES, 20 k, 5%, 0.1 W, 0603; Manufacturer: Vishay-Dale; CompType: Resistor; Value: 20k; Res_ohm: 20000; Value_Code: 20k0; Tolerance_%: 5; Power_W: 0.1; Value2: 0.1W; VDC_V: 75; TempCo: 200 ppm/C; EIA_Code: E24; U/M: EA
R11 = CRCW06033K01FKEA: RES, 3.01 k, 1%, 0.1 W, 0603; Manufacturer: Vishay-Dale; CompType: Resistor; Res_ohm: 3010; Value_Code: 3k01; Tolerance_%: 1; Power_W: 0.1; Value2: 0.1W; VDC_V: 75; TempCo: 100 ppm/C; EIA_Code: E96; U/M: EA; Value: 3.01k
R12 = CRCW060349K9FKEA: RES, 49.9 k, 1%, 0.1 W, 0603; Manufacturer: Vishay-Dale; CompType: Resistor; Value: 49.9k; Res_ohm: 49900; Value_Code: 49k9; Tolerance_%: 1; Power_W: 0.1; Value2: 0.1W; VDC_V: 75; TempCo: 100 ppm/C; EIA_Code: E96; U/M: EA
R13 = CRCW060360K4FKEA: RES, 60.4 k, 1%, 0.1 W, 0603; Manufacturer: Vishay-Dale; CompType: Resistor; Value: 60.4k; Res_ohm: 60400; Value_Code: 60k4; Tolerance_%: 1; Power_W: 0.1; Value2: 0.1W; VDC_V: 75; TempCo: 100 ppm/C; EIA_Code: E96; U/M: EA
R14 R25 = CRCW060324K9FKEA: RES, 24.9 k, 1%, 0.1 W, 0603; Manufacturer: Vishay-Dale; CompType: Resistor; Res_ohm: 24900; Value_Code: 24k9; Tolerance_%: 1; Power_W: 0.1; Value2: 0.1W; VDC_V: 75; TempCo: 100 ppm/C; EIA_Code: E96; U/M: EA; Value: 24.9k
R15 R16 R18 R22 RH1 RH2 RL1 RL2 = CRCW06030000Z0EA: RES, 0 ohm, 5%, 0.1W, 0603; Manufacturer: Vishay-Dale; CompType: Resistor; Value_Code: 0000; Tolerance_%: 5; Power_W: 0.1; VDC_V: 75; TempCo: 200 ppm/C; EIA_Code: E24; U/M: EA
R20 R21 = CRCW06033K30JNEA: RES, 3.3 k, 5%, 0.1 W, 0603; Manufacturer: Vishay-Dale; CompType: Resistor; Value: 3.3k; Res_ohm: 3300; Value_Code: 3k30; Tolerance_%: 5; Power_W: 0.1; Value2: 0.1W; VDC_V: 75; TempCo: 200 ppm/C; EIA_Code: E24; U/M: EA
R23 R29 R33 R104 R105 = CRCW060310K0FKEA: RES, 10.0 k, 1%, 0.1 W, 0603; Manufacturer: Vishay-Dale; CompType: Resistor; Value: 10.0k; Res_ohm: 10000; Value_Code: 10k0; Tolerance_%: 1; Power_W: 0.1; Value2: 0.1W; VDC_V: 75; TempCo: 100 ppm/C; EIA_Code: E96; U/M: EA
R24 = CRCW06038K06FKEA: RES, 8.06 k, 1%, 0.1 W, 0603; Manufacturer: Vishay-Dale; CompType: Resistor; Res_ohm: 8060; Value_Code: 8k06; Tolerance_%: 1; Power_W: 0.1; Value2: 0.1W; VDC_V: 75; TempCo: 100 ppm/C; EIA_Code: E96; U/M: EA; Value: 8.06k
R27 = CRCW06039K53FKEA: RES, 9.53 k, 1%, 0.1 W, 0603; Manufacturer: Vishay-Dale; CompType: Resistor; Value: 9.53k; Res_ohm: 9530; Value_Code: 9k53; Tolerance_%: 1; Power_W: 0.1; Value2: 0.1W; VDC_V: 75; TempCo: 100 ppm/C; EIA_Code: E96; U/M: EA
R30 R32 = CRCW06031K00FKEA: RES, 1.00 k, 1%, 0.1 W, 0603; Manufacturer: Vishay-Dale; CompType: Resistor; Value: 1.00k; Res_ohm: 1000; Value_Code: 1k00; Tolerance_%: 1; Power_W: 0.1; Value2: 0.1W; VDC_V: 75; TempCo: 100 ppm/C; EIA_Code: E96; U/M: EA
R101-R103 = CRCW060347R0JNEA: RES, 47, 5%, 0.1 W, 0603; Manufacturer: Vishay-Dale; CompType: Resistor; Value: 47; Value_Code: 47R0; Tolerance_%: 5; Power_W: 0.1; Value2: 0.1W; VDC_V: 75; TempCo: 200 ppm/C; EIA_Code: E24; U/M: EA
R106 = CRCW060338K3FKEA: RES, 38.3 k, 1%, 0.1 W, 0603; Manufacturer: Vishay-Dale; CompType: Resistor; Value: 38.3k; Res_ohm: 38300; Value_Code: 38k3; Tolerance_%: 1; Power_W: 0.1; Value2: 0.1W; VDC_V: 75; TempCo: 100 ppm/C; EIA_Code: E96; U/M: EA
RS1 = CSNL1206FT2L00: RES, 0.002, 1%, 1 W, 1206; Manufacturer: Stackpole Electronics Inc; CompType: Resistor; Value: 0.002; Tolerance_%: 1; TempCo: 50 ppm/C; U/M: EA; Value_Code: 2L000; Value2: 1W
RS2 RS3 = CSNL2010FT5L00: RES, 0.005, 1%, 1.5 W, 2010; Manufacturer: Stackpole Electronics Inc; CompType: Resistor; Value: 0.005; Tolerance_%: 1; Power_W: 1.5; TempCo: 50 ppm/C; U/M: EA; Value_Code: 5L000; Value2: 1.5W; EIA_Code: E96
RS4 = CSNL2512FT4L00: RES, 0.004, 1%, 2 W, 2512; Manufacturer: Stackpole Electronics Inc; CompType: Resistor; Value: 0.004; Tolerance_%: 1; Power_W: 2; TempCo: 50 ppm/C; U/M: EA; Value_Code: 4L000; Value2: 2W; VDC_V: 200
RS5 = CSNL2010FT1L00: RES, 0.001, 1%, 1.5 W, 2010; Manufacturer: Stackpole Electronics Inc; CompType: Resistor; Value: 0.001; Tolerance_%: 1; Power_W: 1.5; TempCo: 50 ppm/C; U/M: EA; Value_Code: 1L000; Value2: 1.5W; EIA_Code: E96
TP1 TP2 TP7 TP11 = 5000: Test Point, TH, Miniature, Red; Manufacturer: Keystone; CompType: Test Point Loop; U/M: EA
TP3 TP4 TP9 TP12 = 5001: Test Point, TH, Miniature, Black; Manufacturer: Keystone; CompType: Test Point Loop; U/M: EA
TP5 TP6 TP8 TP10 TP13 TP14 = 5002: Test Point, Miniature, White, TH; Manufacturer: Keystone; CompType: Test Point Loop; U/M: EA
U1 = LM5175PWP: 42V Wide VIN 4-Switch Synchronous Buck-Boost Controller, PWP0028F; Alternate Manufacturer: None; Manufacturer: Texas Instruments; SymbolCreator: a0411947; CompType: IC; U/M: EA
U2 U5 U6 = LM431ACM3: Adjustable Precision Zener Shunt Regulator, 3-pin SOT-23; Manufacturer: Texas Instruments; PackageTopMarking: N1F*XTT; PowerWise: N; CompType: MiscPower
U3 U8 = INA199A3RSW: Voltage Output, High or Low Side Measurement, Bi-Directional Zerø-Drift Series Current-Shunt Monitor,  RSW0010A; Manufacturer: Texas Instruments; CompType: IC; U/M: EA
U4 = CMP-0042699-1: 550 uA/Ch, 3 MHz, Rail-to-Rail Output Operational Amplifier, 2.7 to 16 V, -40 to 125 degC, 8-pin SOP (DGK8), Green (RoHS & no Sb/Br); Manufacturer: Texas Instruments; CMRR(Min)(dB): 58; GBW(Typ)(MHz): 2.4; IIB(Max)(pA): 60; Iq per channel(Max)(mA): 0.56; Number of Channels: 2; Packing: LARGE T&R; Rating: Catalog; Slew Rate(Typ)(V/us): 2.1; Sub Family: Low Supply Voltage Amplifier (<=2.7V), Precision Amplifier; Total Supply Voltage(Max)(+5V is 5, +/-5V is 10): 16; Total Supply Voltage(Min)(+5V is 5, +/-5V is 10): 2.7; Vio (25C)(Max)(mV): 5
U7 = SN74LVC1G34DSF: SINGLE BUFFER GATE, DSF0006A; Manufacturer: Texas Instruments; SymbolCreator: a0411947; CompType: IC; U/M: EA
U9 = TPL0102-100RUCR: 256-TAPS DUAL CHANNEL DIGITAL POTENTIOMETER WITH NON-VOLATILE MEMORY, RUC0014A; Manufacturer: Texas Instruments; SymbolCreator: a0411947; CompType: IC; U/M: EA

## Sheet PMP10594_REVA_Sh2.SchDoc
size 431 x 279 mm; Date: Not shown in title block; ApprovedBy: Not shown in title block; CheckedBy: Not shown in title block; Author: Not shown in title block; CompanyName: Not shown in title block; Engineer: Not shown in title block; Organization: Not shown in title block; Address1: Not shown in title block; Address2: Not shown in title block; Address3: Not shown in title block; Address4: Not shown in title block; DocumentNumber: 2; Revision: Use project parameter SCH_Rev; SheetNumber: 2; SheetTotal: 2; PageSetup: Record=PageOptions¦CenterHorizontal=True¦CenterVertical=True¦PrintScale=1.00¦XCorrection=1.00¦YCorrection=1.00¦PrintKind=0¦BorderSize=5000000¦LeftOffset=0¦BottomOffset=0¦Orientation=2¦PaperLength=1000¦PaperWidth=1000¦Scale=100¦PaperSource=15¦PrintQuality=600¦MediaType=1¦DitherType=10¦PaperKind=Letter¦PrintScaleMode=1
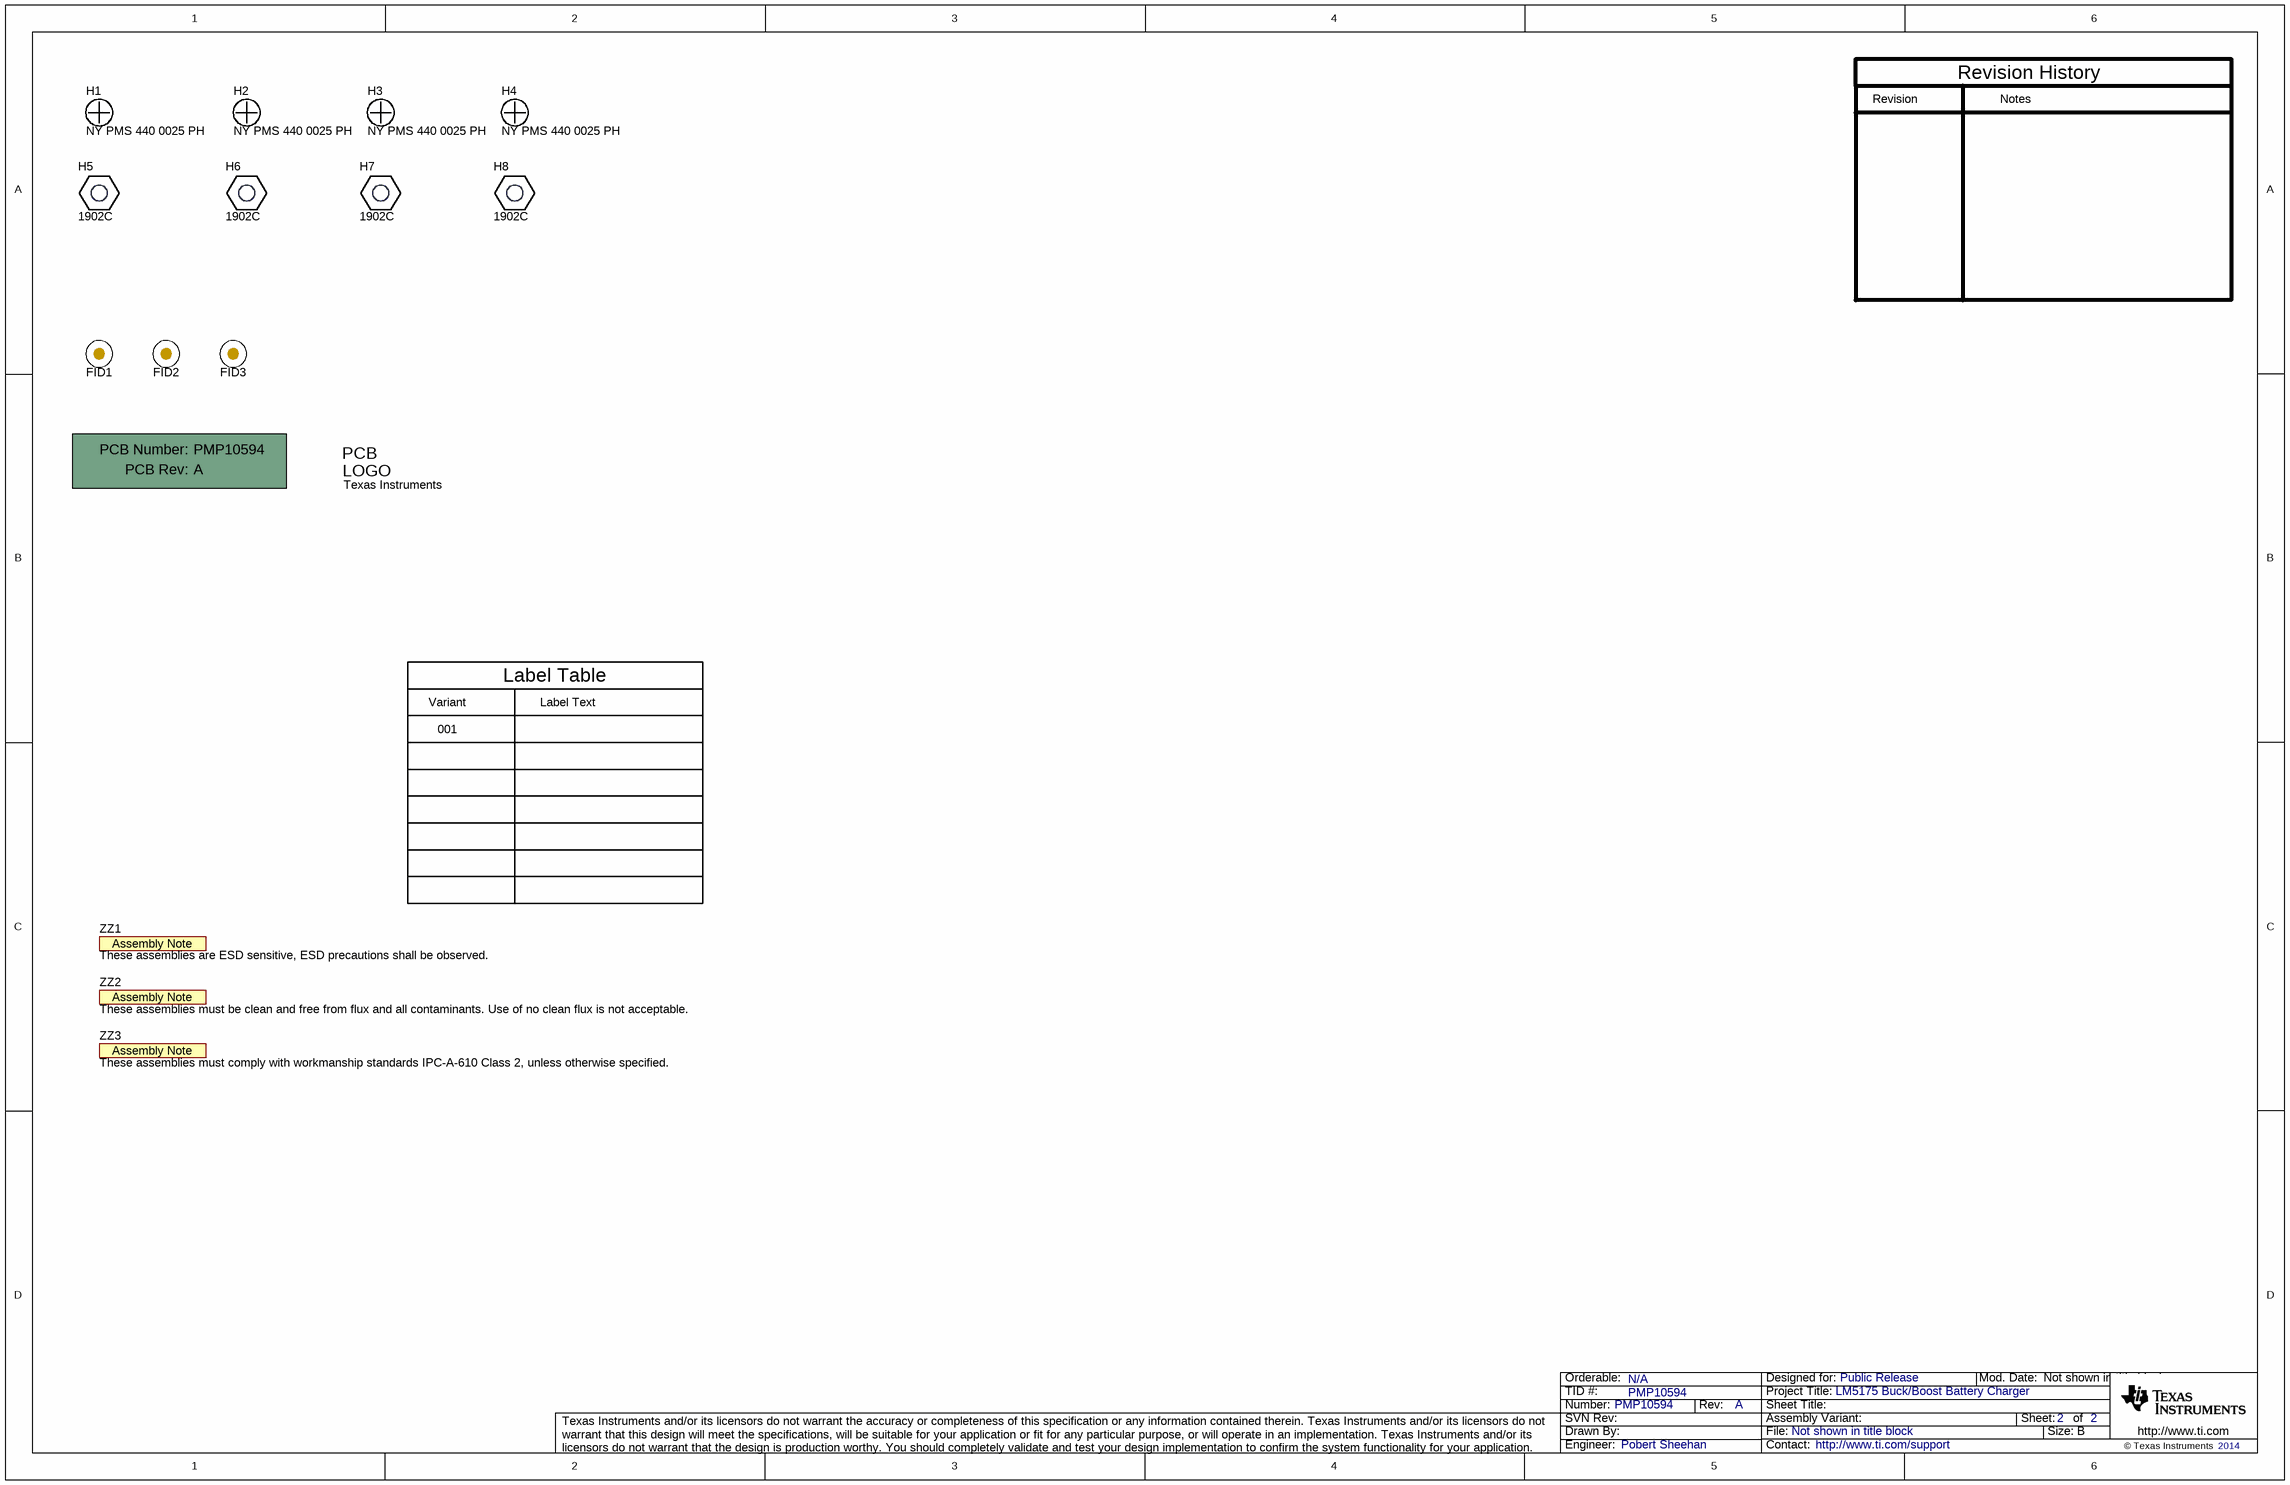
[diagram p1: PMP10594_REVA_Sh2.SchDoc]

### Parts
!PCB1  Printed Circuit Board  (value not drawn)  (mechanical)
FID1  Fiducial  [Fiducial10-20]  (value not drawn)
FID2  Fiducial  [Fiducial10-20]  (value not drawn)
FID3  Fiducial  [Fiducial10-20]  (value not drawn)
H1  NY PMS 440 0025 PH  [NY PMS 440 0025 PH]
H2  NY PMS 440 0025 PH  [NY PMS 440 0025 PH]
H3  NY PMS 440 0025 PH  [NY PMS 440 0025 PH]
H4  NY PMS 440 0025 PH  [NY PMS 440 0025 PH]
H5  1902C  [Keystone_1902C]
H6  1902C  [Keystone_1902C]
H7  1902C  [Keystone_1902C]
H8  1902C  [Keystone_1902C]
Logo1  Texas Instruments  [TI_Stacked_SolderMask_Small]  (no BOM)
ZZ1  These assemblies are ESD sensitive, ESD precautions shall be observed.  [AssemblyNote]  (no BOM)
ZZ2  These assemblies must be clean and free from flux and all contaminants. Use of no clean flux is not acceptable.  [AssemblyNote]  (no BOM)
ZZ3  These assemblies must comply with workmanship standards IPC-A-610 Class 2, unless otherwise specified.  [AssemblyNote]  (no BOM)

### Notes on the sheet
- Revision
- Notes
- Revision History
- Variant
- Label Table
- Label Text
- 001

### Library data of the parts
!PCB1 = PCB: Manufacturer: Any; PartNumber: PMP10594; SymbolCreator: a0412235
FID1-FID3 = Fiducial: Fiducial mark.  There is nothing to buy or mount.; SymbolCreator: codlsc
H1-H4 = NY PMS 440 0025 PH: Machine Screw, Round, #4-40 x 1/4, Nylon, Philips panhead; Manufacturer: B&F Fastener Supply; CompType: Hardware; SymbolCreator: codlsc; U/M: EA
H5-H8 = 1902C: Standoff, Hex, 0.5"L #4-40 Nylon; Manufacturer: Keystone; CompType: Hardware
Logo1 = TI_Logo: Texas Instrument Corporate Signature; SymbolCreator: codlsc
ZZ1-ZZ3 = AssemblyNote: SymbolCreator: codlsc

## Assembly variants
001: not fitted C10 C15 C18 FID1 FID2 FID3 R6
